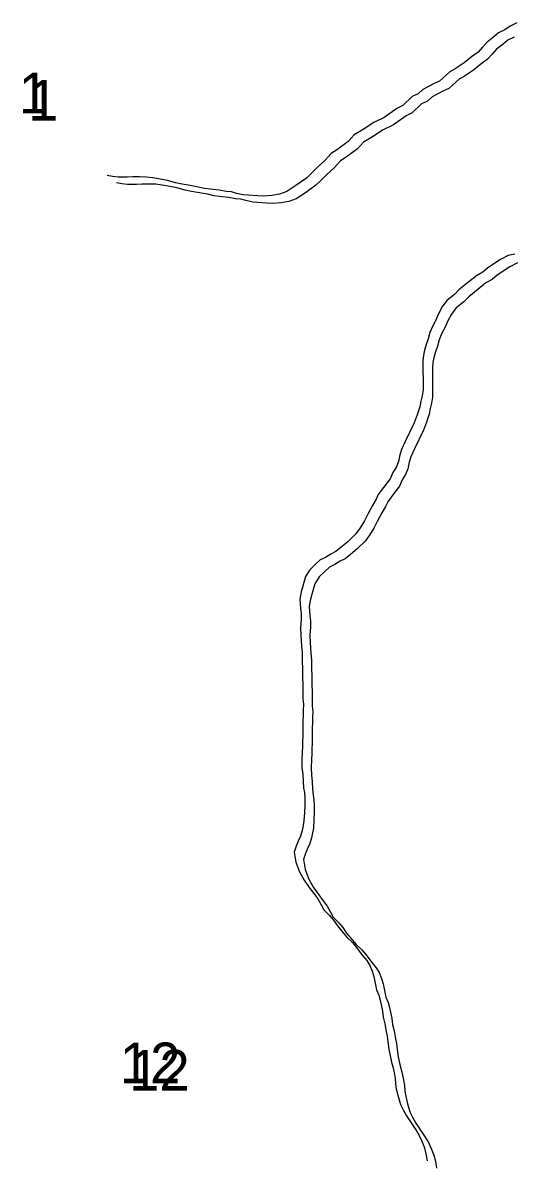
# Model space of a CAD drawing. Extents: x -21.1 to 50.3, y 0 to 22.1.
# Drawn here: x 43.568 to 44.072, y 18.072 to 19.25 of the extents above; entities that cross this region are included whole.
import ezdxf

# ---------------------------------------------------------------- set-up
doc = ezdxf.new("R2010")
doc.units = 0
doc.layers.add('GM_X_Minor_River', color=7, linetype='Continuous')
doc.layers.add('GM_X_Section_Text', color=7, linetype='Continuous')

msp = doc.modelspace()

# ---------------------------------------------------------------- linework, layer by layer
at = {"layer": 'GM_X_Minor_River'}
for points in [[(44.0769, 19.2499), (44.0701, 19.2464), (44.0644, 19.2426), (44.058, 19.2395), (44.0531, 19.2356), (44.0463, 19.2302), (44.0414, 19.2249), (44.0369, 19.2199), (44.0301, 19.2149), (44.0225, 19.2088), (44.0134, 19.2026), (44.0077, 19.1995), (43.9972, 19.1899), (43.9919, 19.1876), (43.9801, 19.1814), (43.9752, 19.1768), (43.9692, 19.1741), (43.9594, 19.1649), (43.9533, 19.1618), (43.9401, 19.1526), (43.9295, 19.1475), (43.9185, 19.1402), (43.9094, 19.1348), (43.903, 19.1279), (43.8913, 19.1191), (43.8856, 19.1156), (43.8792, 19.1083), (43.8713, 19.1011), (43.8657, 19.0957), (43.8604, 19.0903), (43.8494, 19.0826), (43.84, 19.0765), (43.8324, 19.0737), (43.8244, 19.0722), (43.816, 19.0717), (43.8096, 19.072), (43.8005, 19.0727), (43.7951, 19.0731), (43.7883, 19.0745), (43.7829, 19.076), (43.7776, 19.0763), (43.7704, 19.0778), (43.7609, 19.0789), (43.7551, 19.0796), (43.7487, 19.081), (43.7403, 19.0825), (43.7323, 19.084), (43.7254, 19.0854), (43.7171, 19.0876), (43.7079, 19.0895), (43.7018, 19.0905), (43.6953, 19.0913), (43.6881, 19.0916), (43.6813, 19.0915), (43.6756, 19.0911), (43.6661, 19.091), (43.6604, 19.0917), (43.655, 19.0928)], [(44.0741, 19.2351), (44.0676, 19.232), (44.0627, 19.2281), (44.0559, 19.2227), (44.051, 19.2174), (44.0465, 19.2124), (44.0397, 19.2074), (44.0321, 19.2013), (44.0231, 19.1951), (44.0174, 19.192), (44.0068, 19.1824), (44.0015, 19.1801), (43.9898, 19.1739), (43.9849, 19.1693), (43.9788, 19.1666), (43.969, 19.1574), (43.963, 19.1543), (43.9497, 19.1451), (43.9391, 19.14), (43.9282, 19.1327), (43.9191, 19.1273), (43.9127, 19.1204), (43.901, 19.1116), (43.8953, 19.1081), (43.8889, 19.1008), (43.881, 19.0936), (43.8753, 19.0882), (43.87, 19.0828), (43.8591, 19.0751), (43.8496, 19.069), (43.842, 19.0662), (43.8341, 19.0647), (43.8257, 19.0642), (43.8192, 19.0645), (43.8101, 19.0652), (43.8048, 19.0656), (43.7979, 19.067), (43.7926, 19.0685), (43.7872, 19.0688), (43.78, 19.0703), (43.7705, 19.0714), (43.7648, 19.0721), (43.7583, 19.0735), (43.7499, 19.075), (43.7419, 19.0765), (43.7351, 19.0779), (43.7267, 19.0801), (43.7176, 19.082), (43.7115, 19.083), (43.705, 19.0838), (43.6978, 19.0841), (43.6909, 19.084), (43.6852, 19.0836), (43.6757, 19.0835), (43.67, 19.0842), (43.6647, 19.0853)], [(44.0747, 19.0118), (44.0679, 19.0106), (44.06, 19.0064), (44.0471, 18.9979), (44.0418, 18.9933), (44.0354, 18.9898), (44.0275, 18.9833), (44.0176, 18.9756), (44.0127, 18.9703), (44.0048, 18.9641), (43.9999, 18.9576), (43.9962, 18.9507), (43.9932, 18.9435), (43.9902, 18.9381), (43.9872, 18.9313), (43.9854, 18.9248), (43.9835, 18.9191), (43.9817, 18.913), (43.9806, 18.908), (43.9802, 18.9023), (43.9805, 18.8723), (43.9794, 18.8662), (43.9779, 18.8608), (43.9768, 18.8548), (43.9742, 18.8467), (43.9713, 18.8384), (43.9619, 18.8193), (43.9582, 18.8109), (43.9563, 18.8055), (43.9549, 18.7987), (43.9526, 18.7926), (43.9493, 18.7872), (43.9463, 18.7807), (43.9395, 18.7719), (43.9342, 18.7647), (43.932, 18.7597), (43.9283, 18.7532), (43.9234, 18.7444), (43.92, 18.7376), (43.9155, 18.7303), (43.911, 18.7242), (43.9027, 18.7161), (43.8959, 18.7104), (43.8903, 18.7061), (43.8853, 18.7034), (43.8797, 18.7), (43.8744, 18.6973), (43.8695, 18.693), (43.8638, 18.6873), (43.8593, 18.6804), (43.8563, 18.6705), (43.8549, 18.6644), (43.8534, 18.6568), (43.8539, 18.6477), (43.8547, 18.642), (43.8547, 18.6359), (43.854, 18.6275), (43.8545, 18.6199)], [(44.0775, 19.0031), (44.0696, 18.9989), (44.0567, 18.9904), (44.0515, 18.9858), (44.045, 18.9823), (44.0371, 18.9758), (44.0273, 18.9681), (44.0224, 18.9628), (44.0144, 18.9566), (44.0096, 18.9501), (44.0058, 18.9432), (44.0028, 18.936), (43.9998, 18.9306), (43.9968, 18.9238), (43.995, 18.9173), (43.9931, 18.9116), (43.9913, 18.9055), (43.9902, 18.9005), (43.9899, 18.8948), (43.9901, 18.8648), (43.989, 18.8587), (43.9876, 18.8533), (43.9865, 18.8473), (43.9839, 18.8392), (43.9809, 18.8309), (43.9716, 18.8118), (43.9678, 18.8034), (43.966, 18.798), (43.9645, 18.7912), (43.9623, 18.7851), (43.9589, 18.7797), (43.9559, 18.7732), (43.9491, 18.7644), (43.9439, 18.7572), (43.9416, 18.7522), (43.9379, 18.7457), (43.933, 18.7369), (43.9297, 18.7301), (43.9252, 18.7228), (43.9207, 18.7167), (43.9124, 18.7086), (43.9056, 18.7029), (43.8999, 18.6986), (43.895, 18.6959), (43.8893, 18.6925), (43.884, 18.6898), (43.8791, 18.6855), (43.8734, 18.6798), (43.8689, 18.6729), (43.866, 18.663), (43.8645, 18.6569), (43.863, 18.6493), (43.8635, 18.6402), (43.8643, 18.6345), (43.8644, 18.6284), (43.8637, 18.62), (43.8641, 18.6124)], [(43.8545, 18.6199), (43.8549, 18.6146), (43.855, 18.6085), (43.8558, 18.602), (43.856, 18.5762), (43.8564, 18.569), (43.8566, 18.5545), (43.857, 18.5488), (43.8567, 18.5427), (43.8567, 18.5378), (43.8564, 18.5313), (43.8565, 18.5157), (43.8562, 18.5108), (43.8562, 18.5051), (43.8559, 18.4998), (43.8556, 18.491), (43.8556, 18.4838), (43.8565, 18.4766), (43.8569, 18.4693), (43.8573, 18.4629), (43.8581, 18.4579), (43.8586, 18.4522), (43.8586, 18.4446), (43.8583, 18.4374), (43.8576, 18.429), (43.8569, 18.4241), (43.8558, 18.4188), (43.854, 18.413), (43.8517, 18.4081), (43.8495, 18.4027), (43.8476, 18.3966), (43.8492, 18.3864), (43.8531, 18.3765), (43.8578, 18.3678), (43.8631, 18.3603), (43.8678, 18.3542), (43.872, 18.3485), (43.8755, 18.3425), (43.8782, 18.3372), (43.8839, 18.3315), (43.8882, 18.3266), (43.892, 18.3209), (43.8962, 18.3157), (43.9016, 18.3096), (43.9077, 18.3036), (43.9116, 18.2987), (43.9177, 18.2907), (43.9223, 18.2851), (43.9254, 18.2802), (43.9278, 18.2741), (43.9297, 18.2688), (43.9305, 18.2635), (43.9325, 18.2551), (43.9348, 18.2494), (43.936, 18.2445), (43.9384, 18.2331), (43.9392, 18.227), (43.9408, 18.2202), (43.9424, 18.2122), (43.9432, 18.2073), (43.9444, 18.1986), (43.9452, 18.1936), (43.9468, 18.1856), (43.9479, 18.1807), (43.9495, 18.1746), (43.9507, 18.1697), (43.9515, 18.164), (43.9519, 18.1583), (43.9527, 18.153), (43.9543, 18.1465), (43.9571, 18.1371), (43.9598, 18.1314), (43.9632, 18.1253), (43.9694, 18.1162), (43.9729, 18.1109), (43.9763, 18.1053), (43.9791, 18.0992), (43.9818, 18.0924), (43.9833, 18.0863), (43.9845, 18.0791)], [(43.8641, 18.6124), (43.8645, 18.6071), (43.8646, 18.601), (43.8654, 18.5945), (43.8656, 18.5687), (43.8661, 18.5615), (43.8662, 18.547), (43.8666, 18.5413), (43.8663, 18.5352), (43.8663, 18.5303), (43.866, 18.5238), (43.8661, 18.5082), (43.8658, 18.5033), (43.8659, 18.4976), (43.8655, 18.4923), (43.8652, 18.4835), (43.8653, 18.4763), (43.8661, 18.4691), (43.8665, 18.4618), (43.867, 18.4554), (43.8678, 18.4504), (43.8682, 18.4447), (43.8683, 18.4371), (43.8679, 18.4299), (43.8673, 18.4215), (43.8665, 18.4166), (43.8654, 18.4113), (43.8636, 18.4055), (43.8614, 18.4006), (43.8591, 18.3952), (43.8573, 18.3891), (43.8589, 18.3789), (43.8628, 18.369), (43.8674, 18.3603), (43.8728, 18.3528), (43.8774, 18.3467), (43.8816, 18.341), (43.8851, 18.335), (43.8878, 18.3297), (43.8936, 18.324), (43.8978, 18.3191), (43.9016, 18.3134), (43.9059, 18.3082), (43.9112, 18.3021), (43.9174, 18.2961), (43.9212, 18.2912), (43.9274, 18.2832), (43.932, 18.2776), (43.9351, 18.2727), (43.9374, 18.2666), (43.9393, 18.2613), (43.9401, 18.256), (43.9421, 18.2476), (43.9444, 18.2419), (43.9456, 18.237), (43.948, 18.2256), (43.9488, 18.2195), (43.9504, 18.2127), (43.952, 18.2047), (43.9528, 18.1998), (43.954, 18.1911), (43.9548, 18.1861), (43.9564, 18.1781), (43.9576, 18.1732), (43.9592, 18.1671), (43.9603, 18.1622), (43.9611, 18.1565), (43.9616, 18.1508), (43.9624, 18.1455), (43.964, 18.139), (43.9667, 18.1296), (43.9694, 18.1239), (43.9729, 18.1178), (43.979, 18.1087), (43.9825, 18.1034), (43.986, 18.0978), (43.9887, 18.0917), (43.9914, 18.0849), (43.993, 18.0788), (43.9942, 18.0716)]]:
    msp.add_lwpolyline(points, dxfattribs=at)

# ---------------------------------------------------------------- texts
at = {"layer": 'GM_X_Section_Text'}
for s, height, p in [('1', 0.0419, (43.5638, 19.1569)), ('1', 0.0419, (43.5735, 19.1494)), ('12', 0.04186, (43.668, 18.1589)), ('12', 0.04186, (43.6776, 18.1514))]:
    msp.add_text(s, height=height, rotation=0, dxfattribs=at).set_placement(p)

doc.saveas('drawing.dxf')
